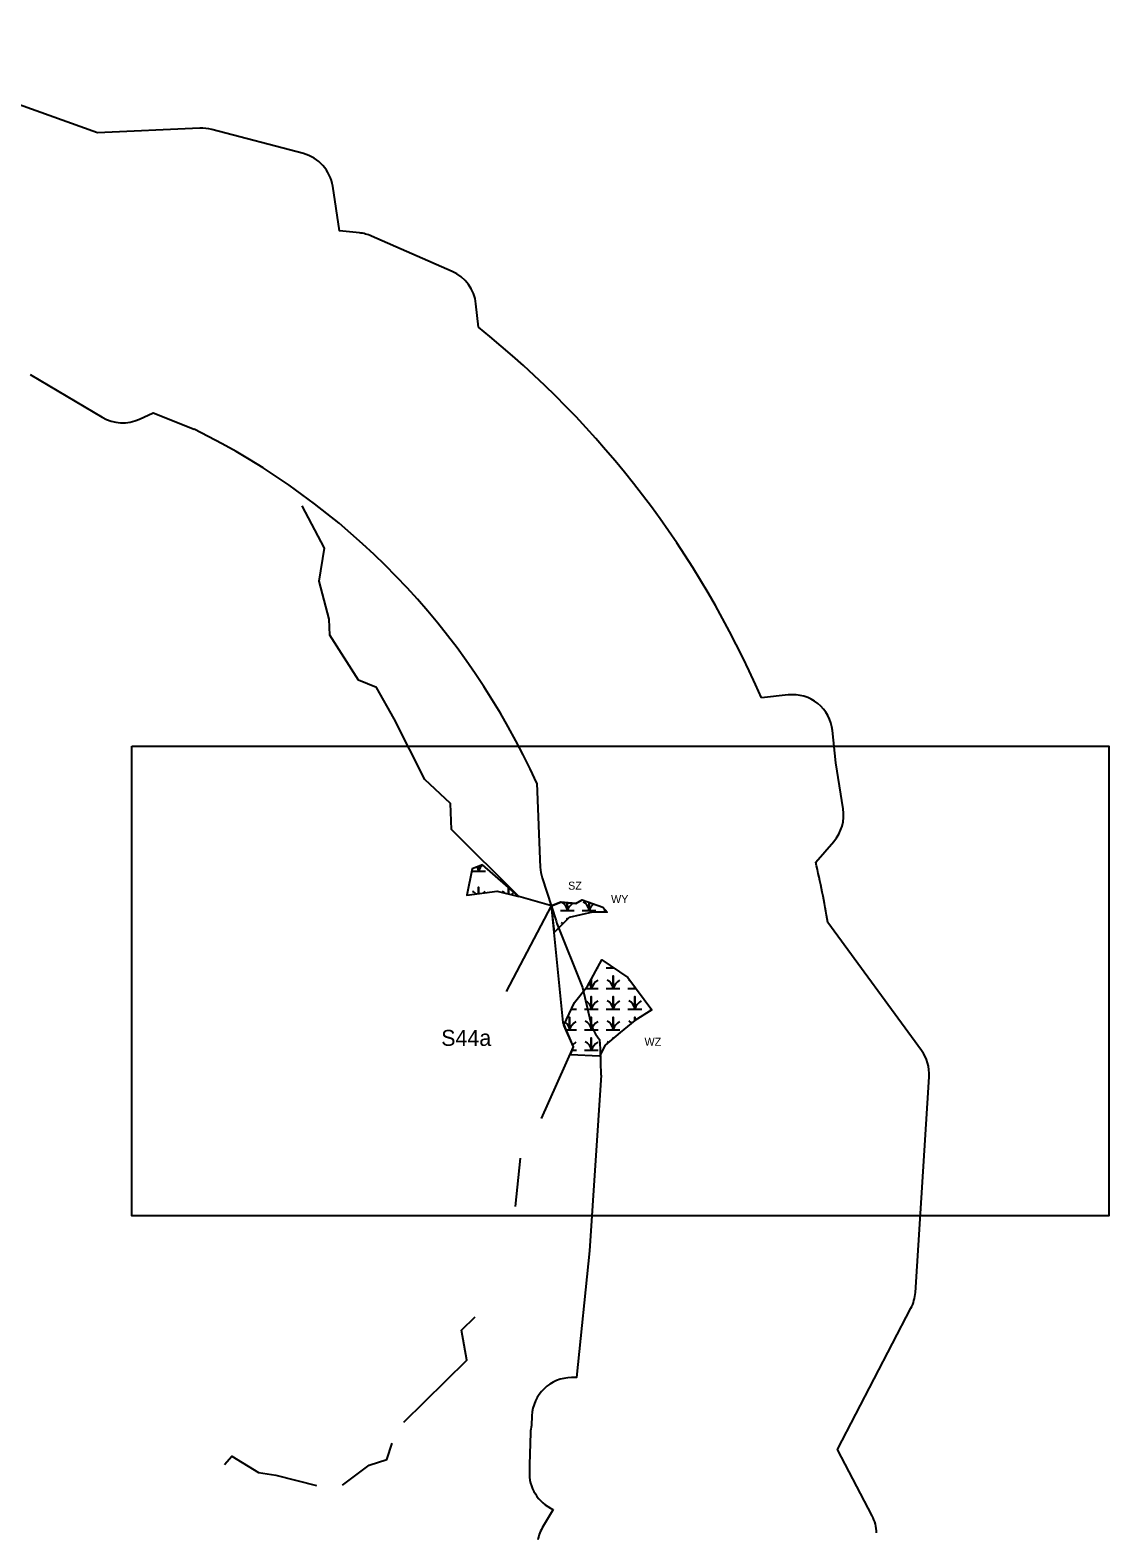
# Model space of a CAD drawing. Extents: x 1253697 to 1278588, y 912189 to 981699.
# Drawn here: x 1263135 to 1264483, y 936349 to 938227 of the extents above; entities that cross this region are included whole.
import ezdxf

# ---------------------------------------------------------------- set-up
doc = ezdxf.new("R2010")
doc.units = 0
for name, color, linetype in [('Default', 7, 'Continuous'), ('Exist Environmental Wetland Boundary', 7, 'Continuous'), ('Exist Hydro Jurisdictional Stream or Body of Water Mitigable', 7, 'Continuous'), ('Exist Hydro Jurisdictional Stream or Body of Water Mitigable Cogo Number', 7, 'Continuous')]:
    doc.layers.add(name, color=color, linetype=linetype)

msp = doc.modelspace()

# ---------------------------------------------------------------- linework, layer by layer
at = {"layer": 'Default'}
for p, q in [((1263476.2, 938072.3), (1263361.7, 938102.5)), ((1263476.2, 938072.3), (1263361.7, 938102.5)), ((1263476.2, 938072.3), (1263361.7, 938102.5)), ((1263476.2, 938072.3), (1263361.7, 938102.5)), ((1263662.3, 937925), (1263561.4, 937969.2)), ((1263662.3, 937925), (1263561.4, 937969.2)), ((1263662.3, 937925), (1263561.4, 937969.2)), ((1263662.3, 937925), (1263561.4, 937969.2)), ((1263695.1, 937855.3), (1263691.9, 937884.6)), ((1263695.1, 937855.3), (1263691.9, 937884.6)), ((1263695.1, 937855.3), (1263691.9, 937884.6)), ((1263695.1, 937855.3), (1263691.9, 937884.6)), ((1263134.6, 937796.3), (1263224.7, 937742.8)), ((1263134.6, 937796.3), (1263224.7, 937742.8)), ((1263134.6, 937796.3), (1263224.7, 937742.8)), ((1263134.6, 937796.3), (1263224.7, 937742.8)), ((1264082.3, 937395.8), (1264048.7, 937392.1)), ((1264082.3, 937395.8), (1264048.7, 937392.1)), ((1264082.3, 937395.8), (1264048.7, 937392.1)), ((1264082.3, 937395.8), (1264048.7, 937392.1)), ((1263767.9, 937285.4), (1263772.3, 937180.3)), ((1263767.9, 937285.4), (1263772.3, 937180.3)), ((1263767.9, 937285.4), (1263772.3, 937180.3)), ((1263767.9, 937285.4), (1263772.3, 937180.3)), ((1264116.6, 937186.9), (1264139.1, 937212.8)), ((1264116.6, 937186.9), (1264139.1, 937212.8)), ((1264116.6, 937186.9), (1264139.1, 937212.8)), ((1264116.6, 937186.9), (1264139.1, 937212.8)), ((1263774.7, 937167.2), (1263792, 937113.3)), ((1263774.7, 937167.2), (1263792, 937113.3)), ((1263774.7, 937167.2), (1263792, 937113.3)), ((1263774.7, 937167.2), (1263792, 937113.3)), ((1263730, 937025), (1263786.5, 937132.2)), ((1264248.7, 936951.4), (1264131.8, 937111.2)), ((1264248.7, 936951.4), (1264131.8, 937111.2)), ((1264248.7, 936951.4), (1264131.8, 937111.2)), ((1264248.7, 936951.4), (1264131.8, 937111.2)), ((1263844.7, 936967.3), (1263846.8, 936964.7)), ((1263844.7, 936967.3), (1263846.8, 936964.7)), ((1263844.7, 936967.3), (1263846.8, 936964.7)), ((1263844.7, 936967.3), (1263846.8, 936964.7)), ((1264241.1, 936649.2), (1264258.3, 936918.7)), ((1264241.1, 936649.2), (1264258.3, 936918.7)), ((1264241.1, 936649.2), (1264258.3, 936918.7)), ((1264241.1, 936649.2), (1264258.3, 936918.7)), ((1263761.7, 936494.9), (1263761.2, 936482.9)), ((1263761.7, 936494.9), (1263761.2, 936482.9)), ((1263761.7, 936494.9), (1263761.2, 936482.9)), ((1263761.7, 936494.9), (1263761.2, 936482.9)), ((1263788.5, 936377.9), (1263775.8, 936357)), ((1263788.5, 936377.9), (1263775.8, 936357)), ((1263788.5, 936377.9), (1263775.8, 936357)), ((1263788.5, 936377.9), (1263775.8, 936357))]:
    msp.add_line(p, q, dxfattribs=at)
for points in [[(1263346.7, 938104.1), (1263218.8, 938098.3), (1262928.3, 938202.5), (1262916.3, 938226.6)], [(1263346.7, 938104.1), (1263218.8, 938098.3), (1262928.3, 938202.5), (1262916.3, 938226.6)], [(1263346.7, 938104.1), (1263218.8, 938098.3), (1262928.3, 938202.5), (1262916.3, 938226.6)], [(1263346.7, 938104.1), (1263218.8, 938098.3), (1262928.3, 938202.5), (1262916.3, 938226.6)], [(1263546.2, 937973.1), (1263521.5, 937975.6), (1263512.9, 938031.5)], [(1263546.2, 937973.1), (1263521.5, 937975.6), (1263512.9, 938031.5)], [(1263546.2, 937973.1), (1263521.5, 937975.6), (1263512.9, 938031.5)], [(1263546.2, 937973.1), (1263521.5, 937975.6), (1263512.9, 938031.5)], [(1263271.3, 937740.5), (1263288.3, 937748.4), (1263339.7, 937727.8)], [(1263271.3, 937740.5), (1263288.3, 937748.4), (1263339.7, 937727.8)], [(1263271.3, 937740.5), (1263288.3, 937748.4), (1263339.7, 937727.8)], [(1263271.3, 937740.5), (1263288.3, 937748.4), (1263339.7, 937727.8)], [(1264150.8, 937253.5), (1264141.6, 937310.9), (1264137.5, 937351.2)], [(1264150.8, 937253.5), (1264141.6, 937310.9), (1264137.5, 937351.2)], [(1264150.8, 937253.5), (1264141.6, 937310.9), (1264137.5, 937351.2)], [(1264150.8, 937253.5), (1264141.6, 937310.9), (1264137.5, 937351.2)], [(1263793.1, 937110.1), (1263825.1, 937030), (1263835, 936987.3)], [(1263793.1, 937110.1), (1263825.1, 937030), (1263835, 936987.3)], [(1263793.1, 937110.1), (1263825.1, 937030), (1263835, 936987.3)], [(1263793.1, 937110.1), (1263825.1, 937030), (1263835, 936987.3)], [(1263848.4, 936920.7), (1263833.8, 936701.1), (1263817.7, 936542.7), (1263811.5, 936542.7)], [(1263848.4, 936920.7), (1263833.8, 936701.1), (1263817.7, 936542.7), (1263811.5, 936542.7)], [(1263848.4, 936920.7), (1263833.8, 936701.1), (1263817.7, 936542.7), (1263811.5, 936542.7)], [(1263848.4, 936920.7), (1263833.8, 936701.1), (1263817.7, 936542.7), (1263811.5, 936542.7)], [(1264187, 936370.1), (1264143.8, 936452.6), (1264235.6, 936629.3)], [(1264187, 936370.1), (1264143.8, 936452.6), (1264235.6, 936629.3)], [(1264187, 936370.1), (1264143.8, 936452.6), (1264235.6, 936629.3)], [(1264187, 936370.1), (1264143.8, 936452.6), (1264235.6, 936629.3)], [(1263760.1, 936473.6), (1263759, 936434.1), (1263758.7, 936425.8)], [(1263760.1, 936473.6), (1263759, 936434.1), (1263758.7, 936425.8)], [(1263760.1, 936473.6), (1263759, 936434.1), (1263758.7, 936425.8)], [(1263760.1, 936473.6), (1263759, 936434.1), (1263758.7, 936425.8)]]:
    msp.add_lwpolyline(points, dxfattribs=at)
msp.add_lwpolyline([(1263261.7, 937331.7), (1264483, 937331.7), (1264483, 936745), (1263261.7, 936745)], close=True, dxfattribs=at)
for centre, radius, start, end in [((1263348.9, 938054.1), 50, 75.229, 92.5827), ((1263348.9, 938054.1), 50, 75.229, 92.5827), ((1263348.9, 938054.1), 50, 75.229, 92.5827), ((1263348.9, 938054.1), 50, 75.229, 92.5827), ((1263463.5, 938023.9), 50, 8.6837, 75.229), ((1263463.5, 938023.9), 50, 8.6837, 75.229), ((1263463.5, 938023.9), 50, 8.6837, 75.229), ((1263463.5, 938023.9), 50, 8.6837, 75.229), ((1263541.3, 937923.4), 50, 66.3462, 84.412), ((1263541.3, 937923.4), 50, 66.3462, 84.412), ((1263541.3, 937923.4), 50, 66.3462, 84.412), ((1263541.3, 937923.4), 50, 66.3462, 84.412), ((1263642.2, 937879.2), 50, 6.1706, 66.3462), ((1263642.2, 937879.2), 50, 6.1706, 66.3462), ((1263642.2, 937879.2), 50, 6.1706, 66.3462), ((1263642.2, 937879.2), 50, 6.1706, 66.3462), ((1262938.4, 936911.1), 1210, 23.4223, 51.2918), ((1262938.4, 936911.1), 1210, 23.4223, 51.2918), ((1262938.4, 936911.1), 1210, 23.4223, 51.2918), ((1262938.4, 936911.1), 1210, 23.4223, 51.2918), ((1263250.3, 937785.8), 50, 239.3165, 294.9391), ((1263250.3, 937785.8), 50, 239.3165, 294.9391), ((1263250.3, 937785.8), 50, 239.3165, 294.9391), ((1263250.3, 937785.8), 50, 239.3165, 294.9391), ((1262938.4, 936911.1), 910, 24.2852, 63.8308), ((1262938.4, 936911.1), 910, 24.2852, 63.8308), ((1262938.4, 936911.1), 910, 24.2852, 63.8308), ((1262938.4, 936911.1), 910, 24.2852, 63.8308), ((1264087.8, 937346.1), 50, 5.8483, 96.2422), ((1264087.8, 937346.1), 50, 5.8483, 96.2422), ((1264087.8, 937346.1), 50, 5.8483, 96.2422), ((1264087.8, 937346.1), 50, 5.8483, 96.2422), ((1264101.4, 937245.6), 50, 318.8837, 9.0802), ((1264101.4, 937245.6), 50, 318.8837, 9.0802), ((1264101.4, 937245.6), 50, 318.8837, 9.0802), ((1264101.4, 937245.6), 50, 318.8837, 9.0802), ((1262938.4, 936911.1), 1210, 9.5182, 13.1766), ((1262938.4, 936911.1), 1210, 9.5182, 13.1766), ((1262938.4, 936911.1), 1210, 9.5182, 13.1766), ((1262938.4, 936911.1), 1210, 9.5182, 13.1766), ((1263822.3, 937182.5), 50, 182.4205, 197.8021), ((1263822.3, 937182.5), 50, 182.4205, 197.8021), ((1263822.3, 937182.5), 50, 182.4205, 197.8021), ((1263822.3, 937182.5), 50, 182.4205, 197.8021), ((1263839.6, 937128.6), 50, 197.8021, 201.7604), ((1263839.6, 937128.6), 50, 197.8021, 201.7604), ((1263839.6, 937128.6), 50, 197.8021, 201.7604), ((1263839.6, 937128.6), 50, 197.8021, 201.7604), ((1263883.7, 936998.6), 50, 193.1097, 218.7397), ((1263883.7, 936998.6), 50, 193.1097, 218.7397), ((1263883.7, 936998.6), 50, 193.1097, 218.7397), ((1263883.7, 936998.6), 50, 193.1097, 218.7397), ((1262938.4, 936911.1), 910, 0.6009, 3.3775), ((1262938.4, 936911.1), 910, 0.6009, 3.3775), ((1262938.4, 936911.1), 910, 0.6009, 3.3775), ((1262938.4, 936911.1), 910, 0.6009, 3.3775), ((1264208.4, 936921.9), 50, 356.3638, 36.2004), ((1264208.4, 936921.9), 50, 356.3638, 36.2004), ((1264208.4, 936921.9), 50, 356.3638, 36.2004), ((1264208.4, 936921.9), 50, 356.3638, 36.2004), ((1264191.2, 936652.3), 50, 332.547, 356.3638), ((1264191.2, 936652.3), 50, 332.547, 356.3638), ((1264191.2, 936652.3), 50, 332.547, 356.3638), ((1264191.2, 936652.3), 50, 332.547, 356.3638), ((1263811.7, 936492.7), 50, 90.1446, 177.469), ((1263811.7, 936492.7), 50, 90.1446, 177.469), ((1263811.7, 936492.7), 50, 90.1446, 177.469), ((1263811.7, 936492.7), 50, 90.1446, 177.469), ((1263810.1, 936472.3), 50, 167.8144, 178.4833), ((1263810.1, 936472.3), 50, 167.8144, 178.4833), ((1263810.1, 936472.3), 50, 167.8144, 178.4833), ((1263810.1, 936472.3), 50, 167.8144, 178.4833), ((1263808.6, 936423.6), 50, 177.469, 246.232), ((1263808.6, 936423.6), 50, 177.469, 246.232), ((1263808.6, 936423.6), 50, 177.469, 246.232), ((1263808.6, 936423.6), 50, 177.469, 246.232), ((1264142.7, 936346.9), 50, 1.8333, 27.6411), ((1264142.7, 936346.9), 50, 1.8333, 27.6411), ((1264142.7, 936346.9), 50, 1.8333, 27.6411), ((1264142.7, 936346.9), 50, 1.8333, 27.6411), ((1263818.6, 936331.1), 50, 148.7561, 169.9949), ((1263818.6, 936331.1), 50, 148.7561, 169.9949), ((1263818.6, 936331.1), 50, 148.7561, 169.9949), ((1263818.6, 936331.1), 50, 148.7561, 169.9949)]:
    msp.add_arc(centre, radius, start, end, dxfattribs=at)
at = {"layer": 'Exist Environmental Wetland Boundary'}
for p, q in [((1263700.3, 937183.3), (1263700.3, 937183.3)), ((1263732.4, 937147.1), (1263732.4, 937155)), ((1263732.4, 937155), (1263732.4, 937147.1)), ((1263787.1, 937126.2), (1263787.5, 937126.2)), ((1263851.9, 937126.2), (1263854.1, 937126.2)), ((1263843.9, 937054.8), (1263844.7, 937054.8)), ((1263811.2, 937003.2), (1263817.5, 937003.2)), ((1263909.1, 937003.2), (1263911.2, 937003.2)), ((1263812.3, 936951.7), (1263817.5, 936951.7))]:
    msp.add_line(p, q, dxfattribs=at)
for points in [[(1263700.3, 937183.3), (1263687.1, 937178.3), (1263680.6, 937145.4), (1263718.6, 937150.7), (1263745.3, 937143.7)], [(1263786.5, 937132.2), (1263798.1, 937136.8), (1263816.9, 937135.3), (1263824.8, 937139.5), (1263850.6, 937130.6), (1263855.8, 937124.1), (1263837.6, 937124.5), (1263808.3, 937117.8), (1263789.9, 937099.1)], [(1263801.9, 936983.1), (1263815.1, 937011.6), (1263831.2, 937032), (1263849.4, 937064.7), (1263881.6, 937042.7), (1263911.8, 937002.3), (1263890.5, 936988.8), (1263872.2, 936973.8), (1263853.5, 936958.1), (1263846.2, 936944.4), (1263810.2, 936946.1), (1263814, 936956)]]:
    msp.add_lwpolyline(points, close=True, dxfattribs=at)
for points in [[(1263686.6, 937175.5), (1263695.2, 937175.5), (1263695.2, 937181.4)], [(1263695.2, 937181.4), (1263695.2, 937175.5), (1263703.8, 937175.5)], [(1263695.2, 937147.5), (1263695.2, 937155.5), (1263695.2, 937147.5)], [(1263797.5, 937126.2), (1263806.1, 937126.2), (1263806.1, 937136.2)], [(1263806.1, 937136.2), (1263806.1, 937126.2), (1263814.7, 937126.2)], [(1263824.7, 937126.2), (1263833.3, 937126.2), (1263833.3, 937136.5)], [(1263833.3, 937136.5), (1263833.3, 937126.2), (1263841.9, 937126.2)], [(1263806.1, 937115.6), (1263806.1, 937116.2), (1263806.1, 937115.6)], [(1263854.7, 937054.8), (1263863.3, 937054.8), (1263863.3, 937055.2)], [(1263863.3, 937055.2), (1263863.3, 937054.8), (1263863.9, 937054.8)], [(1263828.8, 937029), (1263836.1, 937029), (1263836.1, 937040.8)], [(1263836.1, 937040.8), (1263836.1, 937029), (1263844.7, 937029)], [(1263854.7, 937029), (1263863.3, 937029), (1263863.3, 937044.8), (1263863.3, 937029), (1263871.9, 937029)], [(1263827.5, 937003.2), (1263836.1, 937003.2), (1263836.1, 937019), (1263836.1, 937003.2), (1263844.7, 937003.2)], [(1263854.7, 937003.2), (1263863.3, 937003.2), (1263863.3, 937019), (1263863.3, 937003.2), (1263871.9, 937003.2)], [(1263881.9, 937029), (1263890.5, 937029), (1263890.5, 937030.8)], [(1263881.9, 937003.2), (1263890.5, 937003.2), (1263890.5, 937019), (1263890.5, 937003.2), (1263899.1, 937003.2)], [(1263890.5, 937030.8), (1263890.5, 937029), (1263891.8, 937029)], [(1263804.4, 936977.4), (1263808.9, 936977.4), (1263808.9, 936993.2), (1263808.9, 936977.4), (1263817.5, 936977.4)], [(1263827.5, 936977.4), (1263836.1, 936977.4), (1263836.1, 936993.2), (1263836.1, 936977.4), (1263844.7, 936977.4)], [(1263854.7, 936977.4), (1263863.3, 936977.4), (1263863.3, 936993.2), (1263863.3, 936977.4), (1263871.9, 936977.4)], [(1263890.5, 936988.8), (1263890.5, 936993.2), (1263890.5, 936988.8)], [(1263827.5, 936951.7), (1263836.1, 936951.7), (1263836.1, 936967.4), (1263836.1, 936951.7), (1263844.7, 936951.7)], [(1263863.3, 936966.3), (1263863.3, 936967.4), (1263863.3, 936966.3)]]:
    msp.add_lwpolyline(points, dxfattribs=at)
for centre, radius, start, end in [((1263682.9, 937174.6), 12.3, 4.1403, 29.8367), ((1263713.4, 937169.5), 19.2, 134.6259, 161.6222), ((1263682.9, 937138.9), 12.3, 41.5364, 67.535), ((1263713.4, 937133.7), 19.2, 122.1274, 130.8114), ((1263720.1, 937138.9), 12.3, 49.2102, 67.535), ((1263750.7, 937133.7), 19.2, 126.7751, 139.7342), ((1263793.8, 937125.3), 12.3, 4.1403, 67.535), ((1263824.3, 937120.1), 19.2, 126.1852, 161.6222), ((1263821, 937125.3), 12.3, 4.1403, 67.535), ((1263851.5, 937120.1), 19.2, 130.9517, 161.6222), ((1263793.8, 937099.5), 12.3, 57.3416, 67.535), ((1263851, 937053.9), 12.3, 4.1403, 6.1765), ((1263881.5, 937048.7), 19.2, 160.5795, 161.6222), ((1263823.8, 937028.1), 12.3, 4.1403, 39.1171), ((1263854.3, 937022.9), 19.2, 122.1274, 161.6222), ((1263851, 937028.1), 12.3, 4.1403, 67.535), ((1263881.5, 937022.9), 19.2, 122.1274, 161.6222), ((1263878.2, 937028.1), 12.3, 58.4987, 67.535), ((1263878.2, 937028.1), 12.3, 4.1403, 15.2393), ((1263908.7, 937022.9), 19.2, 157.7676, 161.6222), ((1263827.1, 936997.2), 19.2, 122.1274, 124.8119), ((1263823.8, 937002.3), 12.3, 4.1403, 67.535), ((1263854.3, 936997.2), 19.2, 122.1274, 161.6222), ((1263851, 937002.3), 12.3, 4.1403, 67.535), ((1263881.5, 936997.2), 19.2, 122.1274, 161.6222), ((1263878.2, 937002.3), 12.3, 4.1403, 67.535), ((1263908.7, 936997.2), 19.2, 122.1274, 161.6222), ((1263796.6, 936976.6), 12.3, 4.1403, 55.5335), ((1263827.1, 936971.4), 19.2, 122.1274, 161.6222), ((1263823.8, 936976.6), 12.3, 4.1403, 67.535), ((1263854.3, 936971.4), 19.2, 122.1274, 161.6222), ((1263851, 936976.6), 12.3, 4.1403, 67.535), ((1263881.5, 936971.4), 19.2, 122.1274, 161.6222), ((1263878.2, 936976.6), 12.3, 47.2029, 67.535), ((1263827.1, 936945.6), 19.2, 122.1274, 137.8339), ((1263823.8, 936950.8), 12.3, 4.1403, 67.535), ((1263854.3, 936945.6), 19.2, 122.1274, 161.6222), ((1263851, 936950.8), 12.3, 58.9803, 67.535)]:
    msp.add_arc(centre, radius, start, end, dxfattribs=at)
at = {"layer": 'Exist Hydro Jurisdictional Stream or Body of Water Mitigable'}
msp.add_line((1263741.5, 936756.3), (1263747.6, 936816.9), dxfattribs=at)
for points in [[(1263774, 936866.3), (1263814, 936956), (1263800.8, 936986.6), (1263786.5, 937132.2), (1263745.3, 937143.7), (1263661.5, 937227.5), (1263660.1, 937260.3), (1263627.9, 937289.9), (1263589.8, 937365.9), (1263567.5, 937405.2), (1263545.2, 937414.4), (1263509.5, 937470.3), (1263508.4, 937490.4), (1263495.9, 937537.9), (1263502.5, 937579.3), (1263474.8, 937631.9)], [(1263786.8, 937129.4), (1263786.5, 937132.2), (1263785.9, 937132.4)], [(1263816.9, 937135.3), (1263798.1, 937136.8), (1263786.5, 937132.2)], [(1263601.6, 936487), (1263680.7, 936564.3), (1263673.9, 936601.9), (1263690.9, 936618.7)], [(1263525.3, 936408.1), (1263558.4, 936433.1), (1263580.7, 936440.2), (1263587, 936460.6)], [(1263377.6, 936434), (1263387, 936444.4), (1263420.3, 936424.2), (1263441.7, 936420.6), (1263492.8, 936407.8)]]:
    msp.add_lwpolyline(points, dxfattribs=at)

# ---------------------------------------------------------------- texts
at = {"layer": 'Exist Environmental Wetland Boundary'}
for s, p in [('WY', (1263860.8, 937135.6)), ('WZ', (1263902.6, 936957.3))]:
    msp.add_text(s, height=10, dxfattribs=at).set_placement(p)
at = {"layer": 'Exist Hydro Jurisdictional Stream or Body of Water Mitigable'}
msp.add_text('SZ', height=10, dxfattribs=at).set_placement((1263807.1, 937152.4))
at = {"layer": 'Exist Hydro Jurisdictional Stream or Body of Water Mitigable Cogo Number'}
msp.add_text('S44a', height=20, dxfattribs=at).set_placement((1263648.5, 936957.2))

doc.saveas('drawing.dxf')
